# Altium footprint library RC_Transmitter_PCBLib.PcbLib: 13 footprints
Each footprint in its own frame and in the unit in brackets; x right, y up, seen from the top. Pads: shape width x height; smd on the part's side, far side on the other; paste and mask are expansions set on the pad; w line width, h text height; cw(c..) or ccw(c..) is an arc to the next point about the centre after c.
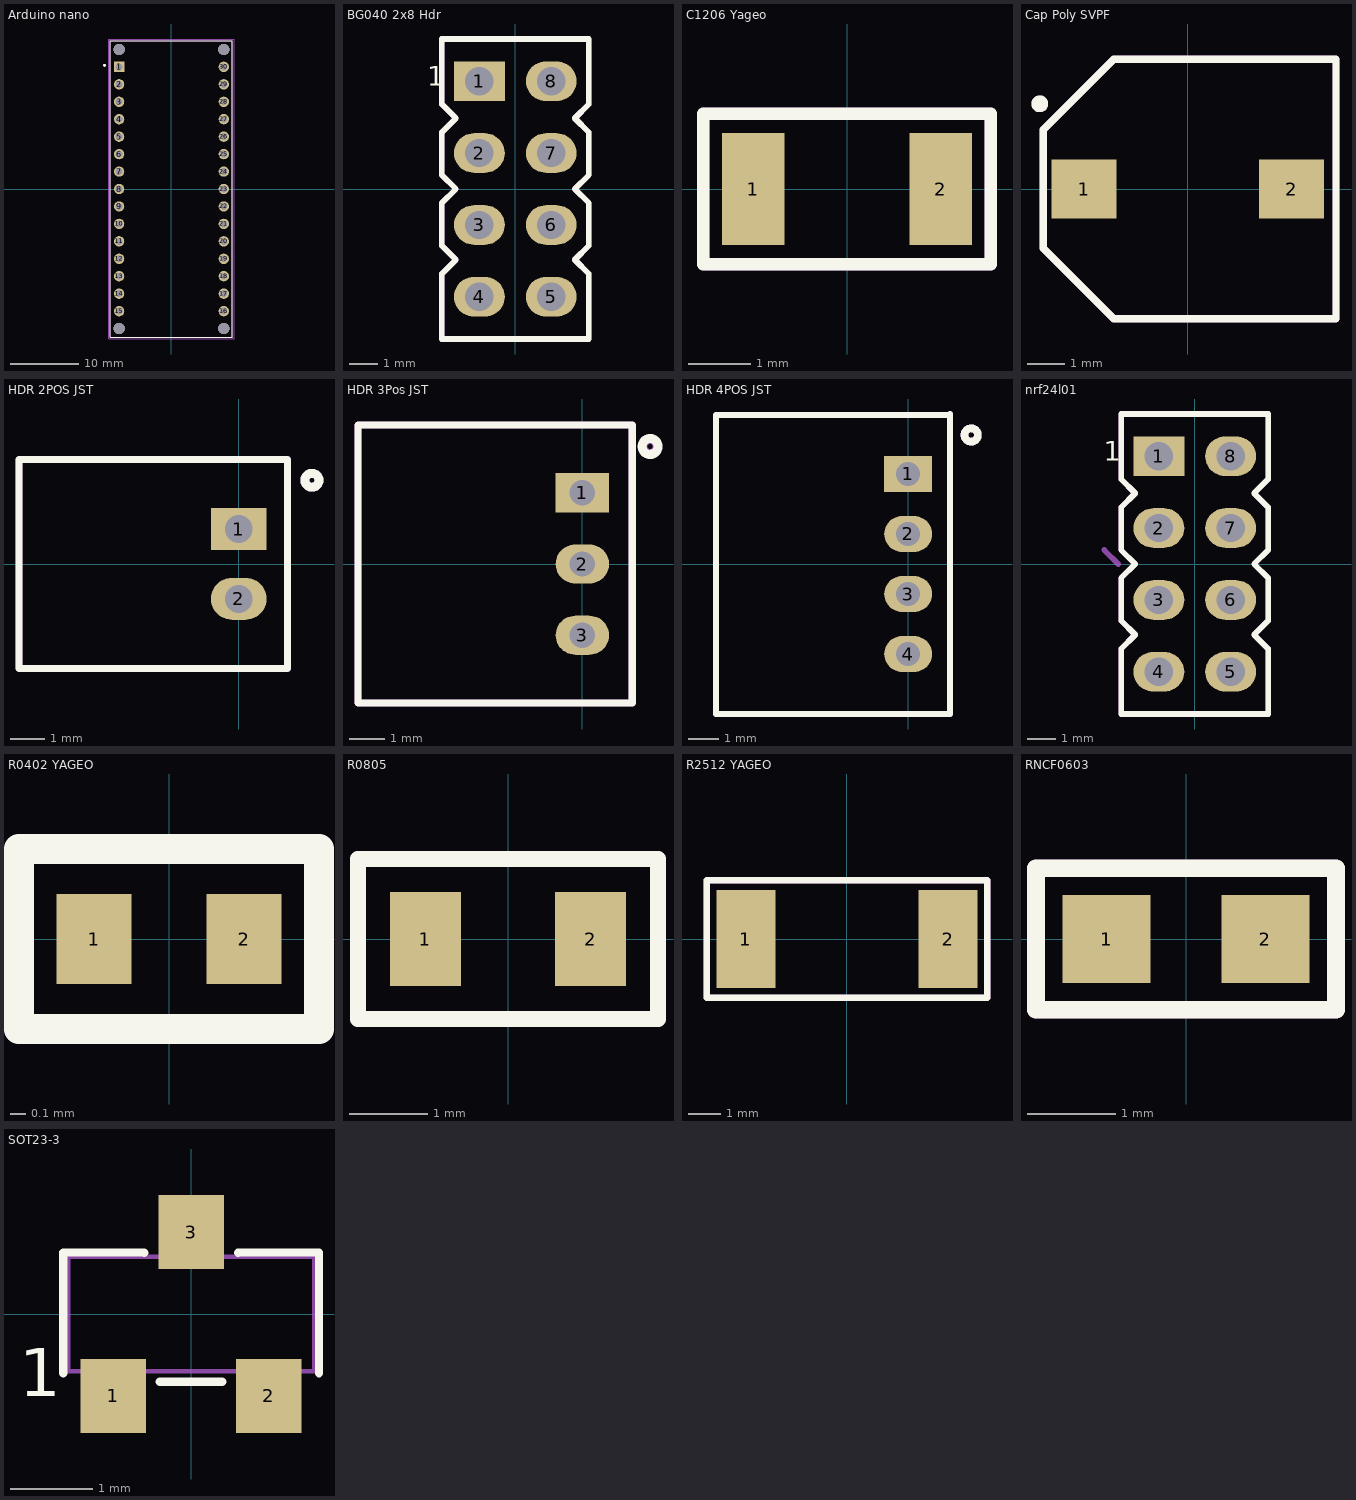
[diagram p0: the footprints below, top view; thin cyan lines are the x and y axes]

## Arduino nano [mm]
pads (34):
  rect 1.508x1.508 hole 1: 1(-7.62,17.78)
  round 1.508 hole 1: 2(-7.62,15.24) 3(-7.62,12.7) 4(-7.62,10.16) 5(-7.62,7.62) 6(-7.62,5.08) 7(-7.62,2.54) 8(-7.62,0) 9(-7.62,-2.54) 10(-7.62,-5.08) 11(-7.62,-7.62) 12(-7.62,-10.16) 13(-7.62,-12.7) 14(-7.62,-15.24) 15(-7.62,-17.78) 16(7.62,-17.78) 17(7.62,-15.24) 18(7.62,-12.7) 19(7.62,-10.16) 20(7.62,-7.62) 21(7.62,-5.08) 22(7.62,-2.54) 23(7.62,0) 24(7.62,2.54) 25(7.62,5.08) 26(7.62,7.62) 27(7.62,10.16) 28(7.62,12.7) 29(7.62,15.24) 30(7.62,17.78)
  round 1.651 hole 1.651 unplated: ""(-7.62,-20.32) ""(-7.62,20.32) ""(7.62,-20.32) ""(7.62,20.32)
Top Overlay:
  circle w0.2: c-9.75,18 r0.1
  lines w0.127: -8.89,-21.59 -8.89,21.59 8.89,21.59 8.89,-21.59 -8.89,-21.59
Mechanical 13:
  circle w0.2: c-9.75,18 r0.1
  lines w0.127: -8.89,-21.59 8.89,-21.59 8.89,21.59 -8.89,21.59 -8.89,-21.59
Mechanical 15:
  lines w0.05: -9.14,-21.84 -9.14,21.84 9.14,21.84 9.14,-21.84 -9.14,-21.84
3D body "A000005.STEP": height 12.61, standoff -5.99, extent -9,-23.4 9,21.6

## BG040 2x8 Hdr [mm]
pads (8):
  rect 1.8x1.4 hole 1: 1(-1.27,3.81)
  oval 1.8x1.4 hole 1: 2(-1.27,1.27) 3(-1.27,-1.27) 4(-1.27,-3.81) 5(1.27,-3.81) 6(1.27,-1.27) 7(1.27,1.27) 8(1.27,3.81)
Top Overlay:
  lines w0.2: -2.6,-2 -2.6,-0.5 -2.1,0 -2.6,0.5 -2.6,2 -2.1,2.5 ; -2.6,-2 -2.1,-2.5 ; -2.6,-2 -2.1,-2.5 ; -2.6,3 -2.6,5.3 2.6,5.3 2.6,3 2.1,2.5 2.6,2 2.6,0.5 2.1,0 2.6,-0.5 2.6,-2 ; -2.6,3 -2.1,2.5 ; -2.6,3 -2.1,2.5 ; -2.1,-2.5 -2.6,-3 -2.6,-5.3 2.6,-5.3 2.6,-3 2.1,-2.5 ; 2.1,-2.5 2.6,-2 ; 2.1,-2.5 2.6,-2
  text "1" at -3.117,3.65 h0.7
Top Assembly:
  lines w0.2: -2.6,-2 -2.6,-0.5 -2.1,0 -2.6,0.5 -2.6,2 -2.1,2.5 ; -2.6,-2 -2.1,-2.5 ; -2.6,-2 -2.1,-2.5 ; -2.6,3 -2.6,5.3 2.6,5.3 2.6,3 2.1,2.5 2.6,2 2.6,0.5 2.1,0 2.6,-0.5 2.6,-2 ; -2.6,3 -2.1,2.5 ; -2.6,3 -2.1,2.5 ; -2.1,-2.5 -2.6,-3 -2.6,-5.3 2.6,-5.3 2.6,-3 2.1,-2.5 ; 2.1,-2.5 2.6,-2 ; 2.1,-2.5 2.6,-2
  text "1" at -3.117,3.65 h0.7
  text ".Designator" at -3.499,-0.233 h0.7
3D body "BG040-08-A-0300-0300-N-G.stp": height 5.55, standoff -2.99, extent -2.5,-5.08 2.5,5.08

## C1206 Yageo [mm]
pads (2):
  rect 1x1.8 smd: 1(-1.5,0) 2(1.5,0)
Top Overlay:
  lines w0.2: -2.3,-1.2 2.3,-1.2 2.3,1.2 -2.3,1.2 -2.3,-1.2
Top Assembly:
  lines w0.2: -2.3,-1.2 2.3,-1.2 2.3,1.2 -2.3,1.2 -2.3,-1.2
  text ".Designator" at -3.499,-0.233 h0.7
3D body "RES_AC1206_YAG.step": height 1.8, standoff 0, extent -1.753,-0.902 1.753,0.902

## Cap Poly SVPF [mm]
pads (2):
  rect 1.75x1.6 smd: 1(-2.8,0) 2(2.8,0)
Top Overlay:
  circle w0.254: c-4,2.3 r0.1
  lines w0.2: -3.9,-1.6 -2,-3.5 4,-3.5 4,3.5 -2,3.5 -3.9,1.6 -3.9,-1.6
Top Assembly:
  circle w0.254: c-4,2.3 r0.1
  lines w0.2: -3.9,-1.6 -2,-3.5 4,-3.5 4,3.5 -2,3.5 -3.9,1.6 -3.9,-1.6
  text ".Designator" at -3.499,-0.233 h0.7
3D body "50SVPF10M.STEP": height 5.91, standoff 0.01, extent -3.65,-3.3 3.65,3.3

## HDR 2POS JST [mm]
pads (2):
  rect 1.6x1.2 hole 0.8: 1(0,1)
  oval 1.6x1.2 hole 0.8: 2(0,-1)
Top Overlay:
  circle w0.254: c2.1,2.4 r0.202
  lines w0.2: -6.3,-3 1.4,-3 1.4,-1.95 1.4,1.925 1.4,3 -6.3,3 -6.3,-3
Top Assembly:
  circle w0.254: c2.1,2.4 r0.202
  lines w0.2: -6.3,-3 1.4,-3 1.4,-1.95 1.4,1.925 1.4,3 -6.3,3 -6.3,-3
  text ".Designator" at -5.799,-0.233 h0.7
3D body "S2B-PH-K-S(LF)(SN)--3DModel-STEP-1.STEP": height 4.81, standoff -3.37, extent -6.25,-2.95 1.35,2.95

## HDR 3Pos JST [mm]
pads (3):
  rect 1.5x1.1 hole 0.71: 1(0,2)
  oval 1.5x1.1 hole 0.71: 2(0,0) 3(0,-2)
Top Overlay:
  circle w0.254: c1.9,3.3 r0.224
  circle w0.254: c1.9,3.3 r0.224
  lines w0.2: -6.3,-3.9 -6.3,3.9 ; -6.3,-3.9 -2,-3.9 ; -6.3,-3.9 -6.3,3.9 ; -6.3,-3.9 -2,-3.9 ; -6.3,3.9 -2,3.9 ; -6.3,3.9 -2,3.9 ; -2,-3.9 1.4,-3.9 ; -2,-3.9 1.4,-3.9 ; -2,3.9 1.4,3.9 ; -2,3.9 1.4,3.9 ; 1.4,-3.9 1.4,3.9 ; 1.4,-3.9 1.4,3.9
Top Assembly:
  circle w0.254: c1.9,3.3 r0.2
  lines w0.2: -6.3,-3.9 -6.3,3.9 ; -6.3,-3.9 -2,-3.9 ; -6.3,-3.9 -6.3,3.9 ; -6.3,-3.9 -2,-3.9 ; -6.3,3.9 -2,3.9 ; -6.3,3.9 -2,3.9 ; -2,-3.9 1.4,-3.9 ; -2,-3.9 1.4,-3.9 ; -2,3.9 1.4,3.9 ; -2,3.9 1.4,3.9 ; 1.4,-3.9 1.4,3.9 ; 1.4,-3.9 1.4,3.9
  text ".Designator" at -6.099,0.667 h0.7
3D body "S3B-PH-K-S-LF--SN---3DModel-STEP-56544.STEP": height 4.81, standoff -3.37, extent -6.25,-3.95 1.35,3.95

## HDR 4POS JST [mm]
pads (4):
  rect 1.6x1.2 hole 0.8: 1(0,3)
  oval 1.6x1.2 hole 0.8: 2(0,1) 3(0,-1) 4(0,-3)
Top Overlay:
  circle w0.254: c2.1,4.3 r0.224
  lines w0.2: -6.4,-5 1.4,-5 1.4,5 1.373,4.973 -6.4,4.973 -6.4,-5
Top Assembly:
  circle w0.254: c2.1,4.3 r0.224
  lines w0.2: -6.4,-5 1.4,-5 1.4,5 1.373,4.973 -6.4,4.973 -6.4,-5
  text ".Designator" at -5.999,-0.233 h0.7
3D body "S4B-PH-K-S(LF)(SN)--3DModel-STEP-56544.STEP": height 4.81, standoff -3.37, extent -6.275,-4.95 1.325,4.95

## nrf24l01 [mm]
pads (8):
  rect 1.8x1.4 hole 1: 1(-1.27,3.81)
  oval 1.8x1.4 hole 1: 2(-1.27,1.27) 3(-1.27,-1.27) 4(-1.27,-3.81) 5(1.27,-3.81) 6(1.27,-1.27) 7(1.27,1.27) 8(1.27,3.81)
Top Overlay:
  lines w0.2: -2.6,-2 -2.1,-2.5 ; -2.6,-2 -2.1,-2.5 ; -2.6,-2 -2.6,-0.5 -2.1,0 -2.6,0.5 -2.6,2 -2.1,2.5 ; -2.6,3 -2.1,2.5 ; -2.6,3 -2.1,2.5 ; -2.6,3 -2.6,5.3 2.6,5.3 2.6,3 2.1,2.5 2.6,2 2.6,0.5 2.1,0 2.6,-0.5 2.6,-2 ; -2.1,-2.5 -2.6,-3 -2.6,-5.3 2.6,-5.3 2.6,-3 2.1,-2.5 ; 2.1,-2.5 2.6,-2 ; 2.1,-2.5 2.6,-2
  text "1" at -3.217,3.65 h0.7
Top Assembly:
  lines w0.2: -3.2,0.5 -2.7,0 ; -2.6,0.5 -2.6,2 -2.1,2.5 ; -2.1,0 -2.6,-0.5 -2.6,-2 ; -2.6,-2 -2.1,-2.5 ; -2.6,-2 -2.1,-2.5 ; -2.6,3 -2.1,2.5 ; -2.6,3 -2.1,2.5 ; -2.6,3 -2.6,5.3 2.6,5.3 2.6,3 2.1,2.5 2.6,2 2.6,0.5 2.1,0 2.6,-0.5 2.6,-2 ; -2.1,-2.5 -2.6,-3 -2.6,-5.3 2.6,-5.3 2.6,-3 2.1,-2.5 ; 2.1,-2.5 2.6,-2 ; 2.1,-2.5 2.6,-2
  text ".Designator" at -3.499,-0.233 h0.7
  text "1" at -3.217,3.65 h0.7
3D body "nrf24l01.STEP": height 13.01, standoff -5.99, extent -3.1,-7.75 45,7.75

## R0402 YAGEO [mm]
pads (2):
  rect 0.5x0.6 smd: 1(-0.5,0) 2(0.5,0)
Top Overlay:
  lines w0.2: -1,-0.6 1,-0.6 1,0.6 -1,0.6 -1,-0.6
Top Assembly:
  lines w0.2: -1,-0.6 1,-0.6 1,0.6 -1,0.6 -1,-0.6
  text ".Designator" at -3.499,-0.233 h0.7
3D body "RES_AC0402_YAG.step": height 0.38, standoff 0, extent -0.521,-0.279 0.521,0.279

## R0805 [mm]
pads (2):
  rect 0.9x1.2 smd: 1(-1.05,0) 2(1.05,0)
Top Overlay:
  lines w0.2: -1.905,-1.016 1.905,-1.016 1.905,1.016 -1.905,1.016 -1.905,-1.016
Top Assembly:
  lines w0.2: -1.905,-1.016 1.905,-1.016 1.905,1.016 -1.905,1.016 -1.905,-1.016
  text ".Designator" at -2.553,-0.25 h0.7
3D body "AC0805FR-07360RL.STEP": height 0.61, standoff 0.01, extent -1,-0.625 1,0.625

## R2512 YAGEO [mm]
pads (2):
  rect 1.8x3 smd: 1(-3.1,0) 2(3.1,0)
Top Overlay:
  lines w0.2: -4.3,-1.8 4.3,-1.8 4.3,1.8 -4.3,1.8 -4.3,-1.8
Top Assembly:
  lines w0.2: -4.3,-1.8 4.3,-1.8 4.3,1.8 -4.3,1.8 -4.3,-1.8
  text ".Designator" at -3.499,-0.233 h0.7
3D body "RC2512JK-07220RL.STEP": height 0.66, standoff 0.01, extent -3.175,-1.55 3.175,1.55

## RNCF0603 [mm]
pads (2):
  rect 1x1 smd: 1(-0.9,0) 2(0.9,0)
Top Overlay:
  lines w0.2: -1.7,-0.8 1.7,-0.8 1.7,0.8 -1.7,0.8 -1.7,-0.8
Top Assembly:
  lines w0.2: -1.7,-0.8 1.7,-0.8 1.7,0.8 -1.7,0.8 -1.7,-0.8
  text ".Designator" at -3.499,-0.233 h0.7
3D body "CRGCQ0603F1K0.STEP": height 0.56, standoff 0.01, extent -0.8,-0.4 0.8,0.4

## SOT23-3 [mm] "2N7002ET1G"
height 1.11
pads (3):
  rect 0.8x0.9 smd mask+0.051: 1(-0.95,-1) 2(0.95,-1) 3(0,1)
Top Overlay:
  lines w0.102: -1.561,-0.724 -1.561,0.75 -0.572,0.748 ; -0.381,-0.825 0.381,-0.825 ; 0.572,0.748 1.561,0.75 1.561,-0.724
  text "1" at -2.1,-1.2 h1
Top Assembly:
  lines w0.051: -1.499,-0.699 -1.499,0.699 1.499,0.699 1.499,-0.699 -1.499,-0.699
  text "1" at -1.216,-0.55 h0.5
  text ".Designator" at -0.55,-0.325 h1.02
3D body "SOT-23.step": height 0.98, standoff -0.01, extent -1.46,-1.313 1.435,1.107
